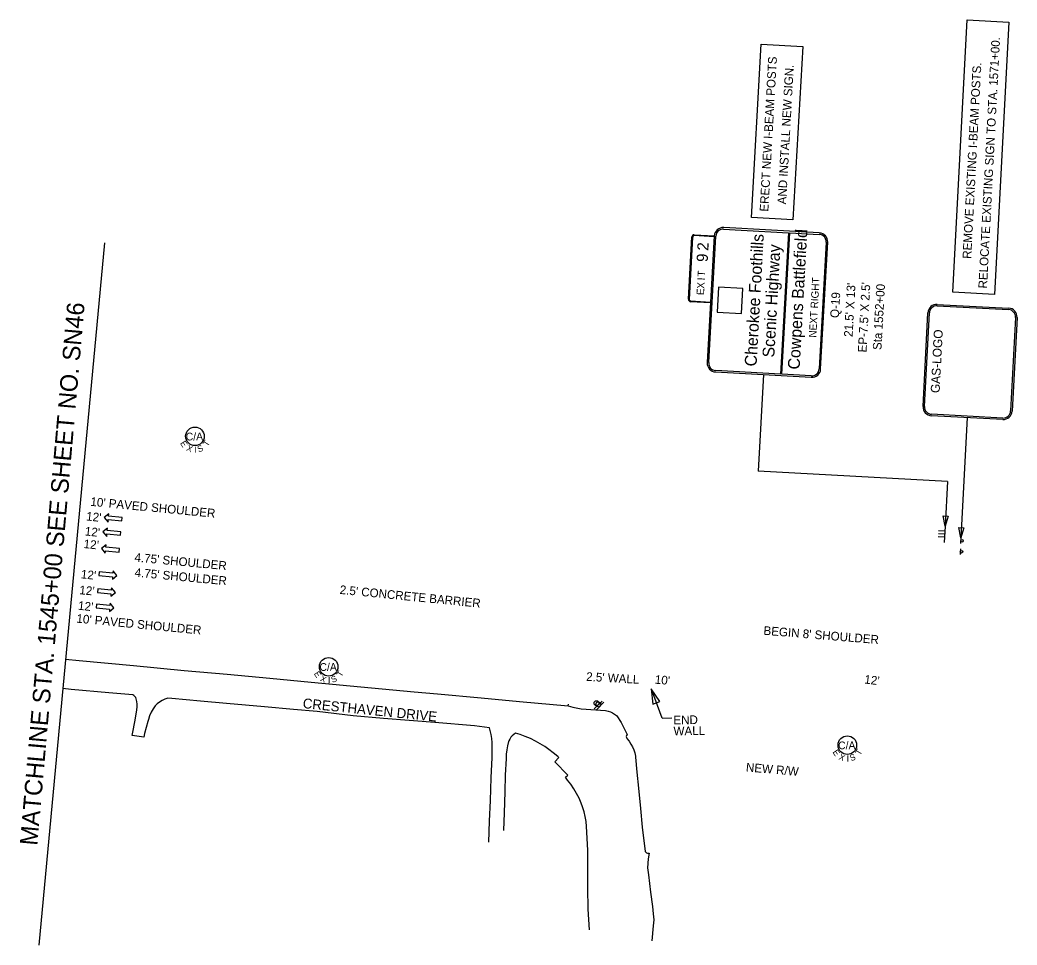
# Model space of a CAD drawing. Extents: x 1801862 to 1803462, y 1187717 to 1188466.
# Drawn here: x 1801862 to 1802666, y 1187720 to 1188466 of the extents above; entities that cross this region are included whole.
import ezdxf

# ---------------------------------------------------------------- set-up
doc = ezdxf.new("R2010")
doc.units = 0
for name, color, linetype in [('RD_EX_BldgApp', 7, 'Continuous'), ('RD_EX_Road', 7, 'Continuous'), ('RD_PD_Final_LnLine', 7, 'Continuous'), ('RD_PD_Final_TX', 7, 'Continuous'), ('RD_PD_RW_TX', 7, 'Continuous'), ('RD_SHT_MatchLine', 7, 'Continuous'), ('RD_SHT_TX', 7, 'Continuous'), ('RD_Sketch8', 7, 'Continuous'), ('RD_TX_RoadID', 7, 'Continuous'), ('SN_P_Signs', 7, 'Continuous'), ('TERMINATOR', 7, 'Continuous')]:
    doc.layers.add(name, color=color, linetype=linetype)

# ---------------------------------------------------------------- blocks, each defined once
blk = doc.blocks.new('SARRW2')
at = {"layer": 'RD_PD_Final_LnLine'}
blk.add_lwpolyline([(-12, 1.2), (-12, -1.2), (-2.83, -1.2), (-2.83, -2.83), (0, 0), (-2.83, 2.83), (-2.83, 1.2)], close=True, dxfattribs=at)

msp = doc.modelspace()

# ---------------------------------------------------------------- linework, layer by layer
at = {"layer": 'RD_EX_BldgApp'}
for p, q in [((1802325.02, 1187910.27), (1802331.38, 1187916.64)), ((1802326.45, 1187909.36), (1802332.82, 1187915.73))]:
    msp.add_line(p, q, dxfattribs=at)
for centre in [(1802326.78, 1187914.9), (1802328.22, 1187913.99)]:
    msp.add_circle(centre, 2, dxfattribs=at)
at = {"layer": 'RD_EX_Road'}
for points in [[(1801898.33, 1187950.39), (1801909.34, 1187949.37), (1801953.34, 1187945.2), (1801994.23, 1187941.4), (1802028.79, 1187938.23), (1802063.13, 1187935.03), (1802096.55, 1187931.9), (1802145.38, 1187927.37), (1802179.58, 1187924.17), (1802198.57, 1187922.4), (1802233.84, 1187919.2), (1802264.64, 1187916.18), (1802304.03, 1187912.63), (1802304.15, 1187913.99)], [(1802239.81, 1187802.63), (1802240.52, 1187819.78), (1802241.2, 1187836.26), (1802241.92, 1187854.7), (1802242.65, 1187870.99), (1802242.54, 1187883.06), (1802242.27, 1187886.32), (1802241.76, 1187889.56), (1802241.02, 1187892.75), (1802240.38, 1187894.89), (1802236.41, 1187895.53), (1802228.39, 1187896.57), (1802196.31, 1187899.18), (1802155.01, 1187902.43), (1802130.36, 1187904.79), (1802101.33, 1187908.1), (1802082.29, 1187909.82), (1802058.89, 1187911.96), (1802043.69, 1187913.32), (1802028.37, 1187914.68), (1802007.4, 1187916.56), (1801984.2, 1187918.63), (1801980.88, 1187918.94), (1801978.56, 1187918.08), (1801976.32, 1187917.01), (1801974.2, 1187915.73), (1801972.22, 1187914.26), (1801970.67, 1187912.88), (1801968.99, 1187910.29), (1801967.51, 1187907.58), (1801966.25, 1187904.76), (1801965.21, 1187901.85), (1801964.72, 1187900.2), (1801963.35, 1187895.3), (1801961.97, 1187890.4), (1801961.54, 1187887.39), (1801952.26, 1187888.85), (1801952.5, 1187890.22), (1801954.57, 1187901.13), (1801955.91, 1187909.62), (1801956.13, 1187911.85), (1801956.12, 1187914.08), (1801955.87, 1187916.3), (1801955.39, 1187918.48), (1801955.38, 1187918.5), (1801954.99, 1187919.47), (1801954.39, 1187920.33), (1801953.61, 1187921.03), (1801952.69, 1187921.54), (1801952.67, 1187921.55), (1801933.32, 1187923.3), (1801902.81, 1187926.07), (1801896.11, 1187926.73)], [(1802304.03, 1187912.63), (1802307.72, 1187911.65), (1802314.3, 1187910.45), (1802334.17, 1187908.87), (1802336.09, 1187908.53), (1802337.96, 1187907.96), (1802339.74, 1187907.17), (1802341.42, 1187906.17), (1802342.97, 1187904.97), (1802343.15, 1187904.81), (1802346.7, 1187899.21), (1802351.48, 1187889.52), (1802351.06, 1187888.87), (1802350.84, 1187888.1), (1802350.88, 1187887.29), (1802351.17, 1187886.55), (1802351.27, 1187886.39), (1802353.03, 1187884.18), (1802354.6, 1187881.84), (1802355.81, 1187879.69), (1802356.81, 1187877.28), (1802357.59, 1187874.78), (1802358.15, 1187872.21), (1802358.29, 1187871.3), (1802359.35, 1187859.3), (1802360.65, 1187846.32), (1802362.36, 1187829.98), (1802363.72, 1187814.91), (1802365.92, 1187795.25), (1802366.49, 1187794.56), (1802367.21, 1187794.08), (1802368.04, 1187793.83), (1802368.9, 1187793.83), (1802369.24, 1187793.89), (1802368.51, 1187789.35), (1802367.92, 1187781.99), (1802368.68, 1187776.34), (1802370.41, 1187762.4), (1802371.91, 1187750.74), (1802372.49, 1187744.92), (1802373, 1187740.17), (1802372.49, 1187735.3), (1802371.41, 1187723.02)], [(1802321.12, 1187731.98), (1802320.13, 1187748.63), (1802319.84, 1187765.94), (1802319.71, 1187779.77), (1802319.68, 1187796.4), (1802318.82, 1187815.27), (1802318.36, 1187819.31), (1802317.66, 1187823.33), (1802316.73, 1187827.3), (1802315.57, 1187831.21), (1802314.46, 1187834.32), (1802312.69, 1187838.26), (1802310.69, 1187842.1), (1802308.5, 1187845.82), (1802306.1, 1187849.42), (1802303.5, 1187852.88), (1802301.7, 1187855.07), (1802303.7, 1187856.86), (1802293.24, 1187867.62), (1802296.52, 1187870.98), (1802295.45, 1187871.96), (1802291.94, 1187874.88), (1802288.28, 1187877.61), (1802285.11, 1187879.83), (1802281.33, 1187882.19), (1802277.43, 1187884.35), (1802273.42, 1187886.3), (1802269.31, 1187888.04), (1802265.12, 1187889.56), (1802261.44, 1187890.67), (1802260.03, 1187889.75), (1802258.75, 1187888.64), (1802257.65, 1187887.37), (1802256.73, 1187885.95), (1802256.02, 1187884.42), (1802255.84, 1187883.91), (1802254.98, 1187880.58), (1802254.34, 1187877.2), (1802253.95, 1187873.78), (1802253.78, 1187870.36), (1802253.08, 1187856.68), (1802252.71, 1187843.45), (1802252.41, 1187826.35), (1802251.73, 1187812.1)]]:
    msp.add_lwpolyline(points, dxfattribs=at)
at = {"layer": 'RD_PD_Final_TX'}
for q in [(1802371.12, 1187926.2), (1802387.65, 1187902.99)]:
    msp.add_line((1802379.8, 1187902.88), q, dxfattribs=at)
at = {"layer": 'RD_SHT_MatchLine'}
msp.add_line((1801929.76, 1188286.36), (1801876.75, 1187719.72), dxfattribs=at)
at = {"layer": 'RD_Sketch8'}
for centre in [(1802002.8, 1188130.24), (1802110.71, 1187944.27), (1802529.16, 1187881.01)]:
    msp.add_circle(centre, 7.5, dxfattribs=at)
at = {"layer": 'SN_P_Signs'}
for p, q in [((1802614.26, 1188246.52), (1802625.77, 1188466.24)), ((1802625.77, 1188466.24), (1802659.34, 1188464.48)), ((1802659.34, 1188464.48), (1802647.83, 1188244.76)), ((1802451.74, 1188306.9), (1802459.56, 1188446.71)), ((1802451.74, 1188306.9), (1802459.56, 1188446.71)), ((1802459.56, 1188446.71), (1802493.12, 1188444.83)), ((1802459.56, 1188446.71), (1802493.12, 1188444.83)), ((1802493.12, 1188444.83), (1802485.3, 1188305.03)), ((1802493.12, 1188444.83), (1802485.3, 1188305.03)), ((1802485.3, 1188305.03), (1802451.74, 1188306.9)), ((1802485.3, 1188305.03), (1802451.74, 1188306.9)), ((1802481.58, 1188294.57), (1802475.2, 1188180.43)), ((1802476.4, 1188180.36), (1802482.78, 1188294.5)), ((1802482.78, 1188294.5), (1802506.49, 1188293.18)), ((1802512.14, 1188286.85), (1802506.43, 1188184.69)), ((1802444.92, 1188249.39), (1802425.26, 1188250.49)), ((1802443.81, 1188229.42), (1802444.92, 1188249.39)), ((1802647.83, 1188244.76), (1802614.26, 1188246.52)), ((1802424.15, 1188230.52), (1802443.81, 1188229.42)), ((1802422.91, 1188182.15), (1802500.04, 1188177.84)), ((1802475.2, 1188180.43), (1802422.98, 1188183.35)), ((1802461.47, 1188180), (1802457.12, 1188102.22)), ((1802500.1, 1188179.04), (1802476.4, 1188180.36)), ((1802625.78, 1188145.33), (1802620.7, 1188048.25)), ((1802610.04, 1188093.66), (1802457.12, 1188102.22)), ((1802610.04, 1188093.66), (1802608.03, 1188057.69)), ((1802607.81, 1188053.78), (1802602.83, 1188054.06)), ((1802608.03, 1188057.69), (1802607.3, 1188044.67)), ((1802607.53, 1188048.77), (1802602.55, 1188049.05)), ((1802607.66, 1188051.18), (1802602.68, 1188051.45)), ((1802620.7, 1188048.25), (1802620.46, 1188043.76)), ((1802620.4, 1188039.38), (1802620.17, 1188034.89)), ((1802325.02, 1187910.27), (1802331.38, 1187916.64)), ((1802326.45, 1187909.36), (1802332.82, 1187915.73))]:
    msp.add_line(p, q, dxfattribs=at)
for points in [[(1802429.36, 1188297.49), (1802481.58, 1188294.57)], [(1802506.55, 1188294.38), (1802429.43, 1188298.69)], [(1802400.95, 1188240.79), (1802403.77, 1188291.11)], [(1802404.36, 1188291.08), (1802401.55, 1188240.76)], [(1802421.8, 1188291.3), (1802405.63, 1188292.21)], [(1802405.66, 1188292.81), (1802421.84, 1188291.9), (1802421.8, 1188291.3)], [(1802421.84, 1188291.9), (1802416.12, 1188189.74)], [(1802417.32, 1188189.68), (1802423.04, 1188291.84)], [(1802507.63, 1188184.63), (1802513.34, 1188286.78)], [(1802425.26, 1188250.49), (1802424.15, 1188230.52)], [(1802402.68, 1188239.49), (1802418.86, 1188238.59), (1802418.82, 1188237.99), (1802402.65, 1188238.89)], [(1802590.21, 1188154.41), (1802594.17, 1188229.9)], [(1802591.41, 1188154.34), (1802595.37, 1188229.84)], [(1802601.67, 1188235.52), (1802659.19, 1188232.5)], [(1802601.73, 1188236.72), (1802659.26, 1188233.7)], [(1802664.87, 1188226.2), (1802660.91, 1188150.7)], [(1802666.07, 1188226.13), (1802662.11, 1188150.64)], [(1802654.54, 1188143.82), (1802597.02, 1188146.84)], [(1802654.61, 1188145.02), (1802597.09, 1188148.04)]]:
    msp.add_lwpolyline(points, dxfattribs=at)
for points in [[(1802610.53, 1188065.76), (1802608.03, 1188057.69), (1802606.44, 1188065.99)], [(1802623.17, 1188056.34), (1802620.7, 1188048.25), (1802619.08, 1188056.55)]]:
    msp.add_lwpolyline(points, close=True, dxfattribs=at)
for centre, radius in [((1802621.59, 1188045.94), 1), ((1802621.3, 1188037.07), 1), ((1802326.78, 1187914.9), 2), ((1802328.22, 1187913.99), 2)]:
    msp.add_circle(centre, radius, dxfattribs=at)
for centre, radius, start, end in [((1802429.03, 1188291.5), 7.2, 86.79793, 176.79793), ((1802429.03, 1188291.5), 6, 86.79793, 176.79793), ((1802506.15, 1188287.19), 7.2, 356.79793, 86.79793), ((1802405.56, 1188291.01), 1.8, 86.79793, 176.79793), ((1802405.56, 1188291.01), 1.2, 86.79793, 176.79793), ((1802506.15, 1188287.19), 6, 356.79793, 86.79793), ((1802402.75, 1188240.69), 1.8, 176.79793, 266.79793), ((1802402.75, 1188240.69), 1.2, 176.79793, 266.79793), ((1802601.36, 1188229.53), 7.2, 86.99984, 176.99984), ((1802601.36, 1188229.53), 6, 86.99984, 176.99984), ((1802658.88, 1188226.51), 6, 356.99984, 86.99984), ((1802658.88, 1188226.51), 7.2, 356.99984, 86.99984), ((1802423.31, 1188189.34), 7.2, 176.79793, 266.79793), ((1802423.31, 1188189.34), 6, 176.79793, 266.79793), ((1802500.44, 1188185.03), 7.2, 266.79793, 356.79793), ((1802500.44, 1188185.03), 6, 266.79793, 356.79793), ((1802597.4, 1188154.03), 7.2, 176.99984, 266.99984), ((1802597.4, 1188154.03), 6, 176.99984, 266.99984), ((1802654.92, 1188151.01), 7.2, 266.99984, 356.99984), ((1802654.92, 1188151.01), 6, 266.99984, 356.99984)]:
    msp.add_arc(centre, radius, start, end, dxfattribs=at)
at = {"layer": 'TERMINATOR'}
msp.add_lwpolyline([(1802377.87, 1187916.26), (1802370.89, 1187926.47), (1802372.25, 1187914.17)], close=True, dxfattribs=at)

# ---------------------------------------------------------------- block references
at = {"layer": 'RD_PD_Final_LnLine'}
for p, xscale, yscale, rotation in [((1801929.65, 1188064.75), 1.1999999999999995, 1.200000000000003, 174.65567699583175), ((1801928.59, 1188053.17), 1.1999999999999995, 1.200000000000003, 174.65567699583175), ((1801927.35, 1188039.59), 1.1999999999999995, 1.200000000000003, 174.65567699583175), ((1801939.85, 1188017.99), 1.1999999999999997, 1.2000000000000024, -5.34432300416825), ((1801938.59, 1188004.28), 1.1999999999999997, 1.2000000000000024, -5.34432300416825), ((1801937.47, 1187991.91), 1.1999999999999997, 1.2000000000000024, -5.34432300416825)]:
    msp.add_blockref('SARRW2', p, dxfattribs=dict(at, xscale=xscale, yscale=yscale, rotation=rotation))

# ---------------------------------------------------------------- texts
at = {"layer": 'RD_PD_Final_TX'}
for s, rotation, p in [("10' PAVED SHOULDER", 354.54177, (1801918.23, 1188074.2)), ("12'", 354.02886, (1801914.77, 1188062.43)), ("12'", 353.95121, (1801913.67, 1188050.33)), ("12'", 354.02886, (1801912.74, 1188040.17)), ("4.75' SHOULDER", 354.65568, (1801953.82, 1188029.24)), ("12'", 353.95121, (1801910.51, 1188015.71)), ("4.75' SHOULDER", 354.65568, (1801953.93, 1188017.04)), ("12'", 354.88698, (1801909.32, 1188002.87)), ("2.5' CONCRETE BARRIER", 354.40741, (1802119.37, 1188003.12)), ("12'", 353.95121, (1801908.2, 1187990.39)), ("10' PAVED SHOULDER", 354.54177, (1801906.95, 1187979.94)), ("BEGIN 8' SHOULDER", 355.37717, (1802461.29, 1187970.16)), ("2.5' WALL", 356.7524, (1802318.3, 1187932.96)), ("10'", 354.76418, (1802373.57, 1187930.71)), ("12'", 353.14978, (1802542.56, 1187930.84)), ('END ', 0.79365, (1802388.84, 1187897.79)), ('WALL', 0.79365, (1802388.96, 1187888.92))]:
    msp.add_text(s, height=7, rotation=rotation, dxfattribs=at).set_placement(p)
at = {"layer": 'RD_PD_RW_TX'}
msp.add_text('NEW R/W', height=7, rotation=355.1019, dxfattribs=at).set_placement((1802447.11, 1187859.86))
at = {"layer": 'RD_SHT_TX'}
msp.add_text('MATCHLINE STA. 1545+00 SEE SHEET NO. SN46', height=14.1726, rotation=84.99841, dxfattribs=at).set_placement((1801875.59, 1187799.63))
at = {"layer": 'RD_Sketch8'}
for s, height, rotation, p in [('C/A', 6.25, 0.54365, (1801995.42, 1188126.89)), ('E', 5, 303.7549, (1801990.63, 1188124.6)), ('T', 5, 58.7288, (1802013.08, 1188121.63)), ('X', 5, 336.18427, (1801995.47, 1188118.99)), ('I', 5, 0.34427, (1802002.27, 1188116.99)), ('S', 5, 22.3361, (1802005.92, 1188117.2)), ('C/A', 6.25, 0.54365, (1802103.33, 1187940.92)), ('E', 5, 303.7549, (1802098.54, 1187938.63)), ('T', 5, 58.7288, (1802120.98, 1187935.66)), ('X', 5, 336.18427, (1802103.37, 1187933.03)), ('I', 5, 0.34427, (1802110.17, 1187931.02)), ('S', 5, 22.3361, (1802113.82, 1187931.23)), ('C/A', 6.25, 0.54365, (1802521.77, 1187877.66)), ('E', 5, 303.7549, (1802516.99, 1187875.37)), ('T', 5, 58.7288, (1802539.43, 1187872.4)), ('X', 5, 336.18427, (1802521.82, 1187869.77)), ('I', 5, 0.34427, (1802528.62, 1187867.76)), ('S', 5, 22.3361, (1802532.27, 1187867.97))]:
    msp.add_text(s, height=height, rotation=rotation, dxfattribs=at).set_placement(p)
at = {"layer": 'RD_TX_RoadID'}
msp.add_text('CRESTHAVEN DRIVE', height=8, rotation=354.16078, dxfattribs=at).set_placement((1802089.51, 1187911.01))
at = {"layer": 'SN_P_Signs'}
for s, height, rotation, p in [('RELOCATE EXISTING SIGN TO STA. 1571+00.', 7, 86.99992, (1802641.81, 1188249.39)), ('ERECT NEW I-BEAM POSTS', 6.9998, 86.79801, (1802465.37, 1188311.38)), ('ERECT NEW I-BEAM POSTS', 6.9998, 86.79801, (1802465.37, 1188311.38)), ('REMOVE EXISTING I-BEAM POSTS.', 7, 86.99992, (1802629.04, 1188273.33)), ('AND INSTALL NEW SIGN.', 6.9998, 86.79801, (1802479.72, 1188317.28)), ('AND INSTALL NEW SIGN.', 6.9998, 86.79801, (1802479.72, 1188317.28)), ('Cowpens Battlefield', 9.6, 86.79793, (1802490.62, 1188183.94)), ('2', 9, 86.79793, (1802416.96, 1188279.81)), ('Cherokee Foothills', 9.6, 86.79793, (1802455.84, 1188186.43)), ('Scenic Highway', 9.6, 86.79793, (1802470.19, 1188193.66)), ('9', 9, 86.79793, (1802416.45, 1188270.73)), ('T', 6, 86.79793, (1802414.29, 1188258.96)), ('X', 6, 86.79793, (1802413.74, 1188249.17)), ('I', 6, 86.79793, (1802414.12, 1188255.98)), ('NEXT RIGHT', 6, 86.79793, (1802504.06, 1188209.74)), ("21.5' X 13'", 7, 86.79801, (1802533.37, 1188210.27)), ("EP-7.5' X 2.5'", 7, 86.79801, (1802544.59, 1188197.77)), ('E', 6, 86.79793, (1802413.45, 1188244.03)), ('Q-19', 7, 86.79801, (1802522.31, 1188225.57)), ('Sta 1552+00', 7, 86.79801, (1802556.62, 1188199.75)), ('GAS-LOGO', 7.2, 86.99984, (1802603.55, 1188165))]:
    msp.add_text(s, height=height, rotation=rotation, dxfattribs=at).set_placement(p)

doc.saveas('drawing.dxf')
